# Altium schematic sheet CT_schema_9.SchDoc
size 254 x 194 mm
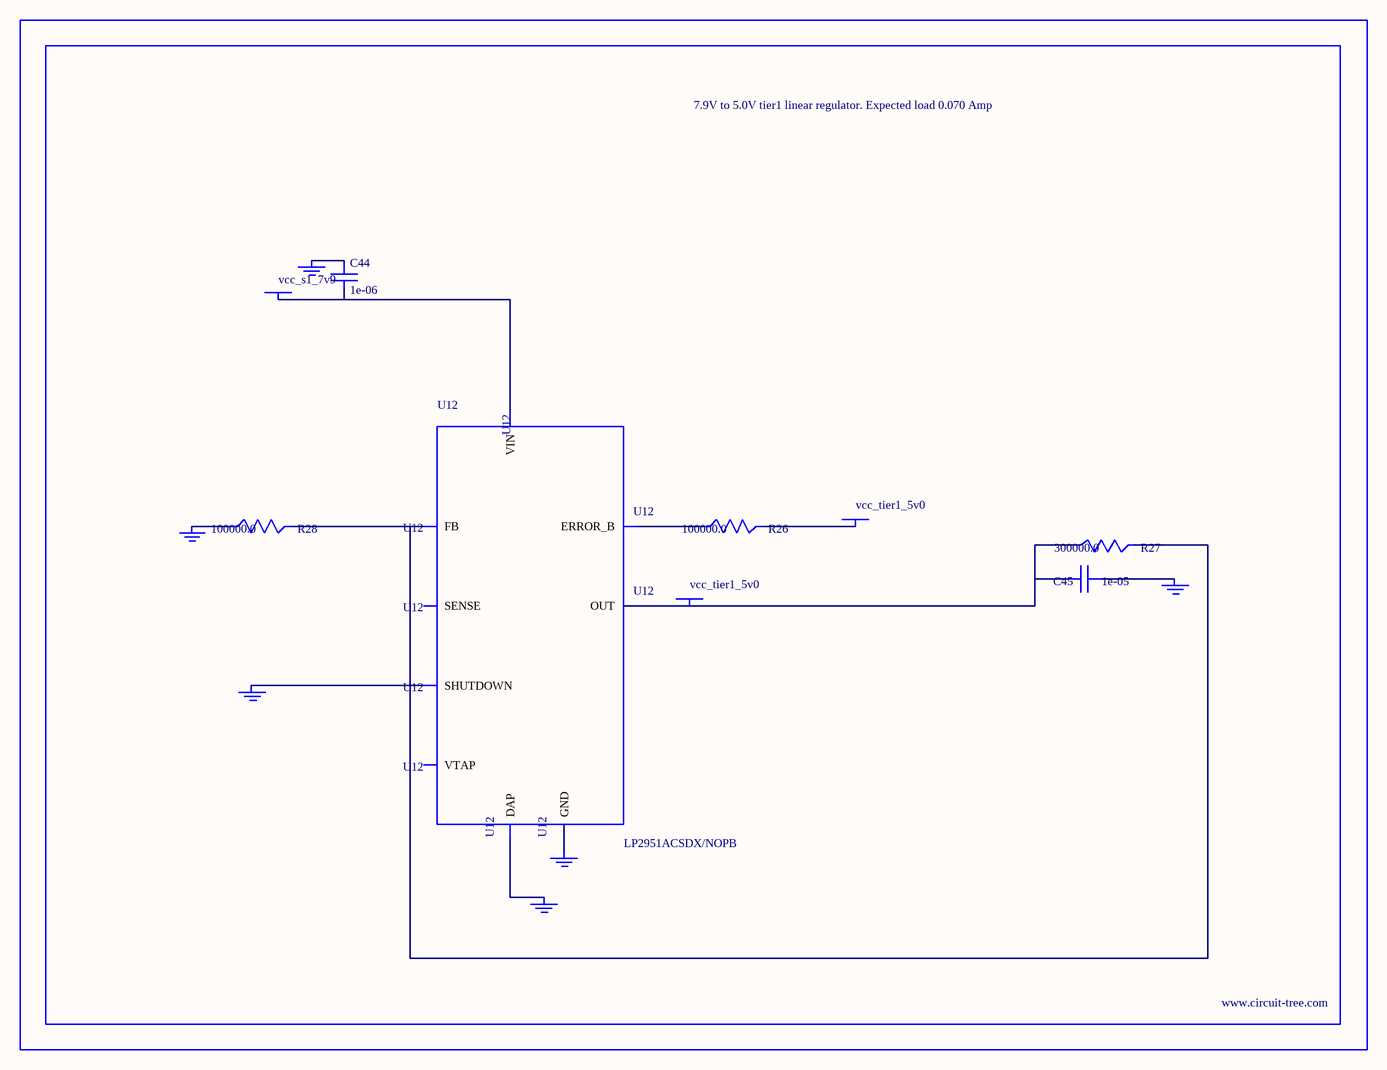
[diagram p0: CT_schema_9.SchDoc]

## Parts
BORDER8  (no value)
C44  1e-06  [C0603]
C45  1e-05  [C1210]
GND_INSTANCE_8_0  (no value)
GND_INSTANCE_8_1  (no value)
GND_INSTANCE_8_2  (no value)
GND_INSTANCE_8_3  (no value)
GND_INSTANCE_8_4  (no value)
GND_INSTANCE_8_5  (no value)
POWER_INSTANCE_8_0  vcc_tier1_5v0
POWER_INSTANCE_8_1  vcc_s1_7v9
POWER_INSTANCE_8_2  vcc_tier1_5v0
R26  100000.0  [R0603]
R27  300000.0  [R0603]
R28  100000.0  [R0603]
U12  LP2951ACSDX/NOPB  [WSON-8]

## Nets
NetC44_1: C44.1 GND_INSTANCE_8_3.0(GND)
NetC44_2: C44.2 POWER_INSTANCE_8_1.0(PWR) U12.8(VIN)
NetC45_1: C45.1 GND_INSTANCE_8_0.0(GND)
NetC45_2: C45.2 POWER_INSTANCE_8_2.0(PWR) R27.1 U12.1(OUT)
NetGND_INSTANCE_8_1_0: GND_INSTANCE_8_1.0(GND) U12.3(SHUTDOWN)
NetGND_INSTANCE_8_2_0: GND_INSTANCE_8_2.0(GND) R28.1
NetGND_INSTANCE_8_4_0: GND_INSTANCE_8_4.0(GND) U12.PAD(DAP)
NetGND_INSTANCE_8_5_0: GND_INSTANCE_8_5.0(GND) U12.4(GND)
NetPOWER_INSTANCE_8_0_0: POWER_INSTANCE_8_0.0(PWR) R26.2
NetR26_1: R26.1 U12.5(ERROR_B)
NetR27_2: R27.2 R28.2 U12.7(FB)

Not connected (* = marked no-connect by the designer): U12 2(SENSE) 6(VTAP)

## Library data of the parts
BORDER8 = BORDER_PAGE8
C44 = C0603C105K3RACTU
C45 = GRM32DR61E106MA12L
GND_INSTANCE_8_0-GND_INSTANCE_8_5 = GND
POWER_INSTANCE_8_0-POWER_INSTANCE_8_2 = PWR
R26 R28 = RC0603JR-07100KL
R27 = RC0603JR-07300KL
